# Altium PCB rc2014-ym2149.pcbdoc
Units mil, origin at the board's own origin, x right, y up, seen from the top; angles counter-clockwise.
Board outline 4542.51 x 2488.19 mil, 2 copper layers (Top Layer, Bottom Layer); 37 components, 100 nets, 242 pads, 3 vias.
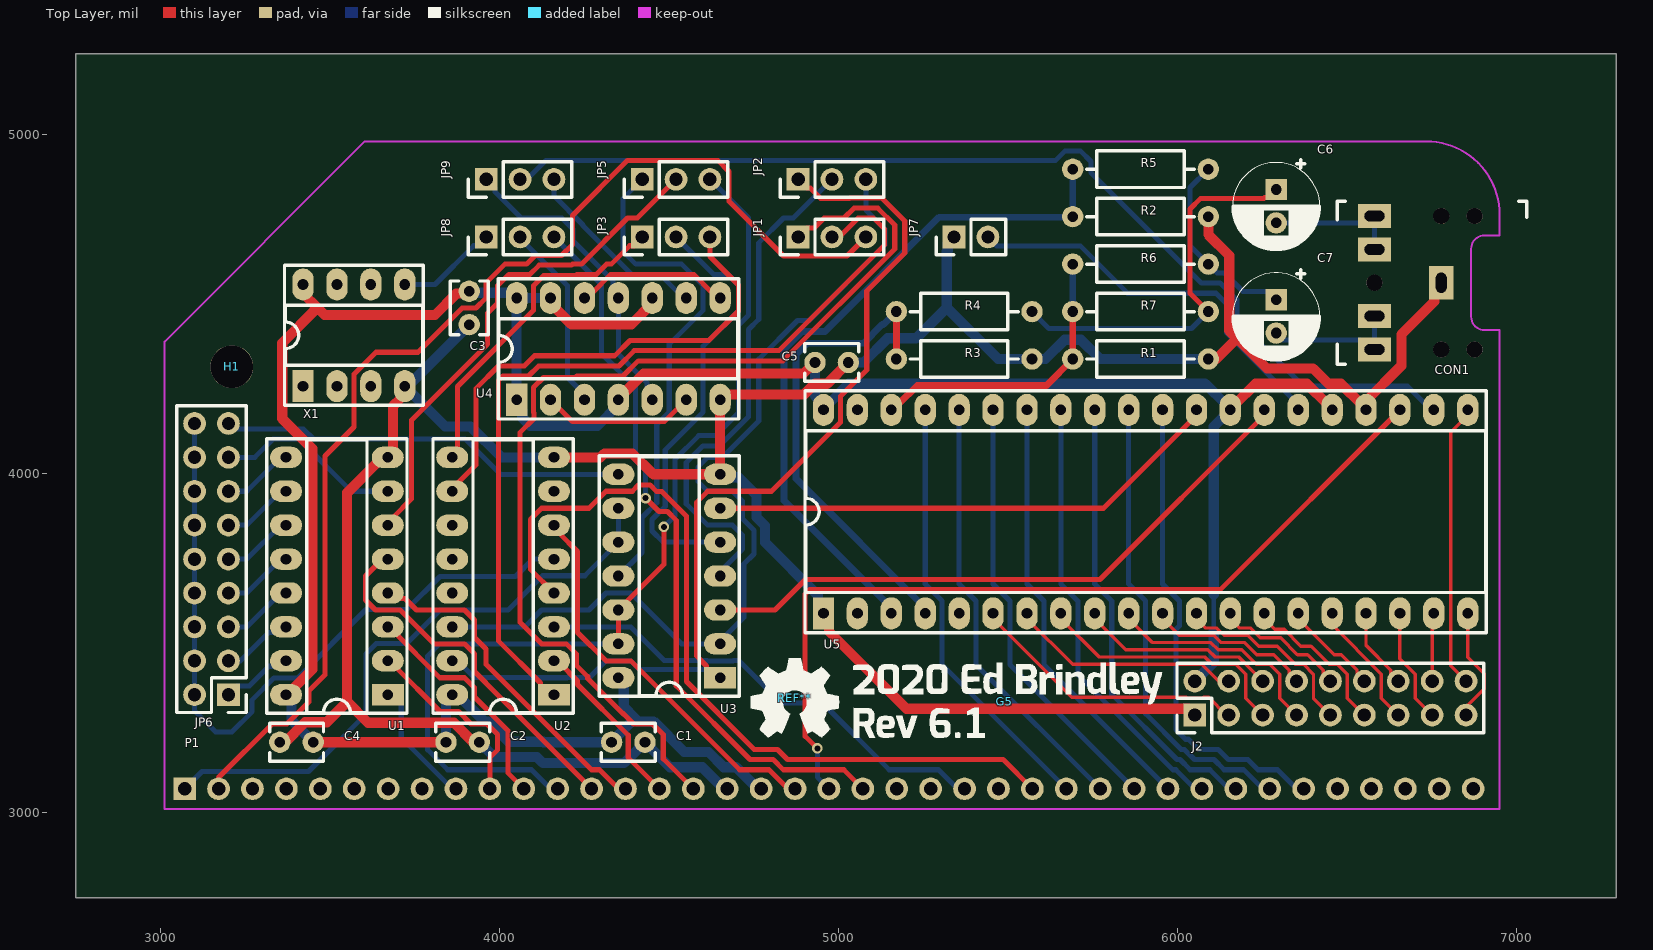
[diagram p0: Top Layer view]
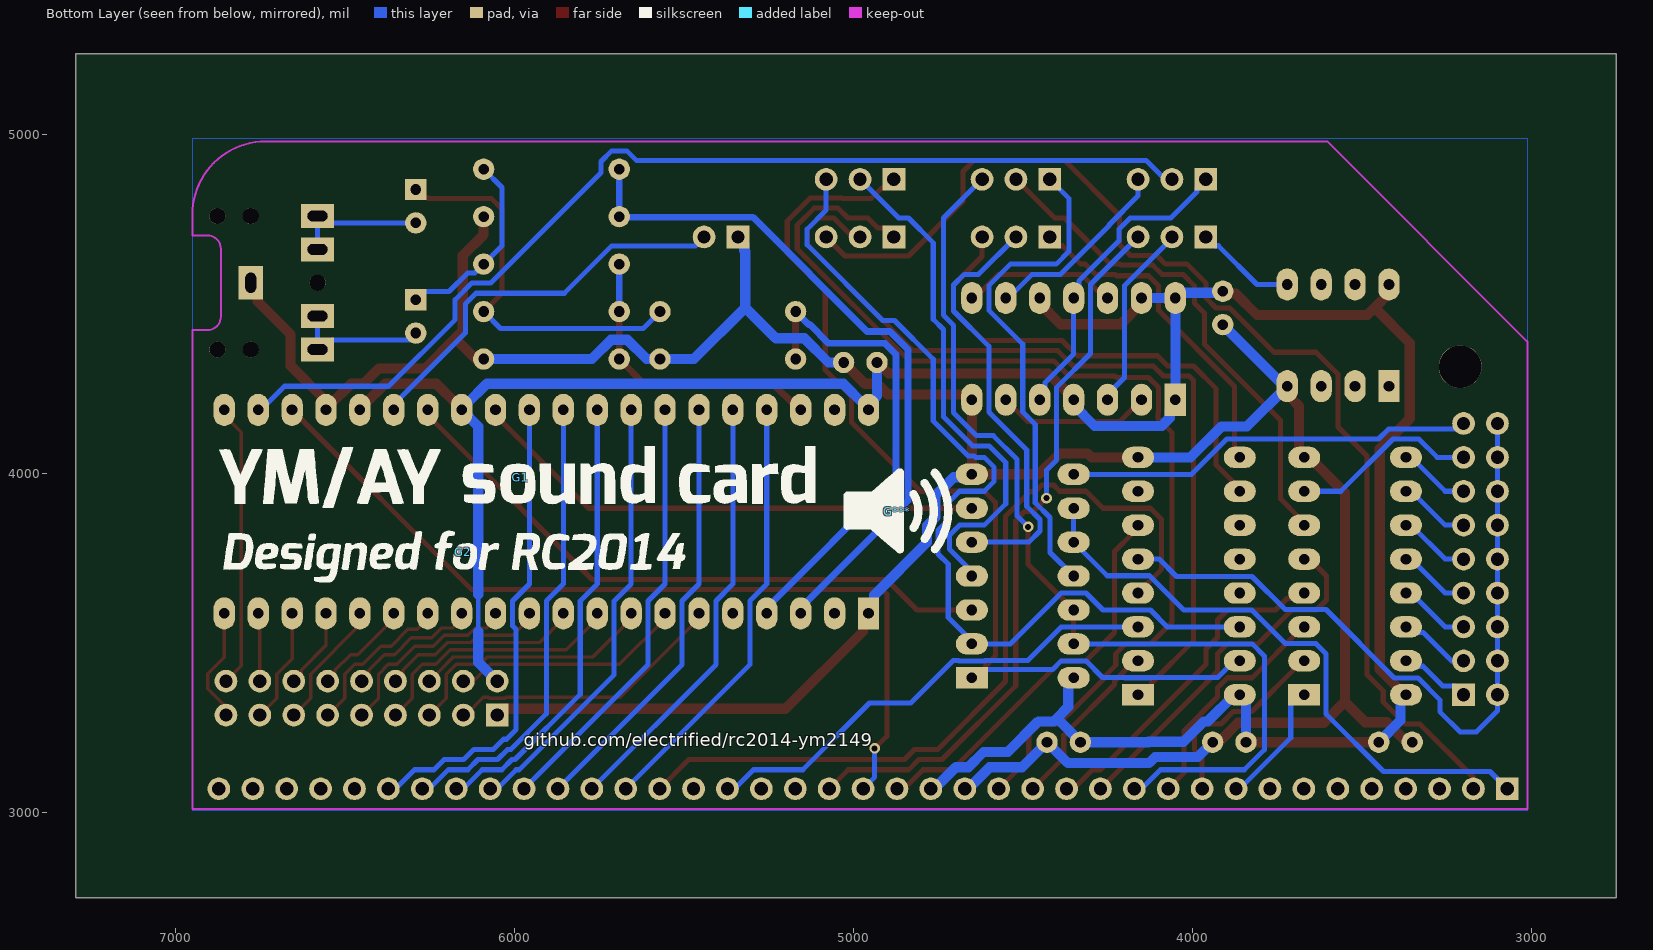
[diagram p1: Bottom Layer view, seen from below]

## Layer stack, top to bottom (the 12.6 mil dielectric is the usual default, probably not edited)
Top Layer: signal copper (thickness not stored)
Dielectric: dielectric 12.6, FR-4, Dk 4.8
Bottom Layer: signal copper (thickness not stored)

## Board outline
7292.51,2750 2750,2750 2750,5238.19 7292.51,5238.19

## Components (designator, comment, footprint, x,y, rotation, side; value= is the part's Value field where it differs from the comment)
C1 "0.1uF" Capacitor_THT:C_Disc_D3.8mm_W2.6mm_P2.50mm 4329.92,3208.19 r0 top
C2 "0.1uF" Capacitor_THT:C_Disc_D3.8mm_W2.6mm_P2.50mm 3841.49,3208.19 r0 top
C3 "0.1uF" Capacitor_THT:C_Disc_D3.8mm_W2.6mm_P2.50mm 3909.92,4538.19 r270 top
C4 "0.1uF" Capacitor_THT:C_Disc_D3.8mm_W2.6mm_P2.50mm 3449.92,3208.19 r180 top
C5 "0.1uF" Capacitor_THT:C_Disc_D3.8mm_W2.6mm_P2.50mm 4929.92,4328.19 r0 top
C6 "4.7uF" Capacitor_THT:CP_Radial_D6.3mm_P2.50mm 6289.91,4838.19 r270 top
C7 "4.7uF" Capacitor_THT:CP_Radial_D6.3mm_P2.50mm 6289.91,4513.19 r270 top
CON1 "SJ1-3523N" rc2014:Headphone_Jack_3.5mm_5_pin 6579.91,4563.19 r180 top
G1 "LOGO" rc2014:ym_text2 5979.92,3988.19 r180 bottom
G2 "LOGO" rc2014:designed_for_rc2014 6149.91,3768.19 r180 bottom
G5 "LOGO" rc2014:rev61 5489.92,3328.19 r0 top
G*** "LOGO" rc2014:speaker 4869.92,3888.19 r180 bottom
H1 "MountingHole" MountingHole:MountingHole_3.2mm_M3 3209.92,4315.67 r0 top
J2 "IO Out" Connector_PinHeader_2.54mm:PinHeader_2x09_P2.54mm_Vertical 6049.92,3288.19 r90 top
JP1 "MSX/ZX Spectrum" Connector_PinHeader_2.54mm:PinHeader_1x03_P2.54mm_Vertical 4879.92,4698.19 r90 top
JP2 "MSX/ZX Spectrum" Connector_PinHeader_2.54mm:PinHeader_1x03_P2.54mm_Vertical 4879.92,4868.19 r90 top
JP3 "MSX/ZX Spectrum" Connector_PinHeader_2.54mm:PinHeader_1x03_P2.54mm_Vertical 4419.92,4698.19 r90 top
JP5 "Upper/lower half" Connector_PinHeader_2.54mm:PinHeader_1x03_P2.54mm_Vertical 4419.92,4868.19 r90 top
JP6 "BASE ADDRESS" Connector_PinHeader_2.54mm:PinHeader_2x09_P2.54mm_Vertical 3199.92,3348.19 r180 top
JP7 "YM 1/2 CLK" Connector_PinHeader_2.54mm:PinHeader_1x02_P2.54mm_Vertical 5339.92,4698.19 r90 top
JP8 "Use bus clock" Connector_PinHeader_2.54mm:PinHeader_1x03_P2.54mm_Vertical 3959.92,4698.19 r90 top
JP9 "CLOCK DIVIDE 1/2 or 1/4" Connector_PinHeader_2.54mm:PinHeader_1x03_P2.54mm_Vertical 3959.92,4868.19 r90 top
P1 "RC2014 BUS" rc2014:PinHeader_1x39_P2.54mm_Vertical 3070.87,3070.87 r90 top
R1 "3K" Resistor_THT:R_Axial_DIN0207_L6.3mm_D2.5mm_P10.16mm_Horizontal 5689.92,4338.19 r0 top
R2 "3K" Resistor_THT:R_Axial_DIN0207_L6.3mm_D2.5mm_P10.16mm_Horizontal 5689.92,4758.19 r0 top
R3 "3K" Resistor_THT:R_Axial_DIN0207_L6.3mm_D2.5mm_P10.16mm_Horizontal 5169.92,4338.19 r0 top
R4 "1K" Resistor_THT:R_Axial_DIN0207_L6.3mm_D2.5mm_P10.16mm_Horizontal 5569.92,4478.19 r180 top
R5 "1K" Resistor_THT:R_Axial_DIN0207_L6.3mm_D2.5mm_P10.16mm_Horizontal 6089.92,4898.19 r180 top
R6 "1K6" Resistor_THT:R_Axial_DIN0207_L6.3mm_D2.5mm_P10.16mm_Horizontal 6089.92,4618.19 r180 top
R7 "1K6" Resistor_THT:R_Axial_DIN0207_L6.3mm_D2.5mm_P10.16mm_Horizontal 6089.92,4478.19 r180 top
REF** "OSHW-Symbol_6.7x6mm_SilkScreen" Symbol:OSHW-Symbol_6.7x6mm_SilkScreen 4869.92,3338.19 r0 top
U1 "74HCT138" Package_DIP:DIP-16_W7.62mm_Socket_LongPads 3669.92,3348.19 r180 top
U2 "74HCT138" Package_DIP:DIP-16_W7.62mm_Socket_LongPads 4159.92,3348.19 r180 top
U3 "74HCT00" Package_DIP:DIP-14_W7.62mm_Socket_LongPads 4649.92,3398.19 r180 top
U4 "74HCT74" Package_DIP:DIP-14_W7.62mm_Socket_LongPads 4049.92,4218.19 r90 top
U5 "YM2149" Package_DIP:DIP-40_W15.24mm_Socket_LongPads 4954.92,3588.19 r90 top
X1 "CXO_DIP8" Package_DIP:DIP-8_W7.62mm_Socket_LongPads 3419.92,4258.19 r90 top

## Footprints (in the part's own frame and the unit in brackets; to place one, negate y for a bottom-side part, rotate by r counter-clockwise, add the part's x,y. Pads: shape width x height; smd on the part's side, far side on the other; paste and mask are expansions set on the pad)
Capacitor_THT:C_Disc_D3.8mm_W2.6mm_P2.50mm [mm]
  round 1.6 hole 0.8: 1(0,0) 2(2.5,0)
  silkscreen extent -0.77,-1.42 3.27,1.42
Capacitor_THT:CP_Radial_D6.3mm_P2.50mm [mm]
  rect 1.6x1.6 hole 0.8: 1(0,0)
  round 1.6 hole 0.8: 2(2.5,0)
  silkscreen extent -2.25,-3.27 4.52,3.27
Connector_PinHeader_2.54mm:PinHeader_1x02_P2.54mm_Vertical [mm]
  rect 1.7x1.7 hole 1: 1(0,0)
  round 1.7 hole 1: 2(0,-2.54)
  silkscreen extent -1.33,-3.87 1.33,1.33
Connector_PinHeader_2.54mm:PinHeader_1x03_P2.54mm_Vertical [mm]
  rect 1.7x1.7 hole 1: 1(0,0)
  round 1.7 hole 1: 2(0,-2.54) 3(0,-5.08)
  silkscreen extent -1.33,-6.41 1.33,1.33
Connector_PinHeader_2.54mm:PinHeader_2x09_P2.54mm_Vertical [mm]
  rect 1.7x1.7 hole 1: 1(0,0)
  round 1.7 hole 1: 2(2.54,0) 3(0,-2.54) 4(2.54,-2.54) 5(0,-5.08) 6(2.54,-5.08) 7(0,-7.62) 8(2.54,-7.62) 9(0,-10.16) 10(2.54,-10.16) 11(0,-12.7) 12(2.54,-12.7) 13(0,-15.24) 14(2.54,-15.24) 15(0,-17.78) 16(2.54,-17.78) 17(0,-20.32) 18(2.54,-20.32)
  silkscreen extent -1.33,-21.65 3.87,1.33
MountingHole:MountingHole_3.2mm_M3 [mm]
  round 3.2 hole 3.2 unplated: 1(0,0)
Package_DIP:DIP-8_W7.62mm_Socket_LongPads [mm]
  rect 2.4x1.6 hole 0.8: 1(0,0)
  oval 2.4x1.6 hole 0.8: 2(0,-2.54) 3(0,-5.08) 4(0,-7.62) 5(7.62,-7.62) 6(7.62,-5.08) 7(7.62,-2.54) 8(7.62,0)
  silkscreen extent -1.44,-9.01 9.06,1.39
Package_DIP:DIP-14_W7.62mm_Socket_LongPads [mm]
  rect 2.4x1.6 hole 0.8: 1(0,0)
  oval 2.4x1.6 hole 0.8: 2(0,-2.54) 3(0,-5.08) 4(0,-7.62) 5(0,-10.16) 6(0,-12.7) 7(0,-15.24) 8(7.62,-15.24) 9(7.62,-12.7) 10(7.62,-10.16) 11(7.62,-7.62) 12(7.62,-5.08) 13(7.62,-2.54) 14(7.62,0)
  silkscreen extent -1.44,-16.63 9.06,1.39
Package_DIP:DIP-16_W7.62mm_Socket_LongPads [mm]
  rect 2.4x1.6 hole 0.8: 1(0,0)
  oval 2.4x1.6 hole 0.8: 2(0,-2.54) 3(0,-5.08) 4(0,-7.62) 5(0,-10.16) 6(0,-12.7) 7(0,-15.24) 8(0,-17.78) 9(7.62,-17.78) 10(7.62,-15.24) 11(7.62,-12.7) 12(7.62,-10.16) 13(7.62,-7.62) 14(7.62,-5.08) 15(7.62,-2.54) 16(7.62,0)
  silkscreen extent -1.44,-19.17 9.06,1.39
Package_DIP:DIP-40_W15.24mm_Socket_LongPads [mm]
  rect 2.4x1.6 hole 0.8: 1(0,0)
  oval 2.4x1.6 hole 0.8: 2(0,-2.54) 3(0,-5.08) 4(0,-7.62) 5(0,-10.16) 6(0,-12.7) 7(0,-15.24) 8(0,-17.78) 9(0,-20.32) 10(0,-22.86) 11(0,-25.4) 12(0,-27.94) 13(0,-30.48) 14(0,-33.02) 15(0,-35.56) 16(0,-38.1) 17(0,-40.64) 18(0,-43.18) 19(0,-45.72) 20(0,-48.26) 21(15.24,-48.26) 22(15.24,-45.72) 23(15.24,-43.18) 24(15.24,-40.64) 25(15.24,-38.1) 26(15.24,-35.56) 27(15.24,-33.02) 28(15.24,-30.48) 29(15.24,-27.94) 30(15.24,-25.4) 31(15.24,-22.86) 32(15.24,-20.32) 33(15.24,-17.78) 34(15.24,-15.24) 35(15.24,-12.7) 36(15.24,-10.16) 37(15.24,-7.62) 38(15.24,-5.08) 39(15.24,-2.54) 40(15.24,0)
  silkscreen extent -1.44,-49.65 16.68,1.39
rc2014:designed_for_rc2014 [mil]
  silkscreen extent -707,-88 654,63
rc2014:Headphone_Jack_3.5mm_5_pin [mm]
  round 1.2 hole 1.2 unplated: 1(-7.5,-5) 2(-5,5) 3(-5,-5) 4(0,0) 5(-7.5,5)
  rect 2.5x1.8 hole 0.8 slot 1.5 at 0 deg: R(0,5) RN(0,2.5) T(0,-5) TN(0,-2.5)
  rect 1.8x2.5 hole 0.8 slot 1.5 at 90 deg: S(-5,0)
  silkscreen extent -11.4,-6.1 2.8,6.1
rc2014:PinHeader_1x39_P2.54mm_Vertical [mm]
  rect 1.7x1.7 hole 1: 1(0,0)
  round 1.7 hole 1: 2(0,-2.54) 3(0,-5.08) 4(0,-7.62) 5(0,-10.16) 6(0,-12.7) 7(0,-15.24) 8(0,-17.78) 9(0,-20.32) 10(0,-22.86) 11(0,-25.4) 12(0,-27.94) 13(0,-30.48) 14(0,-33.02) 15(0,-35.56) 16(0,-38.1) 17(0,-40.64) 18(0,-43.18) 19(0,-45.72) 20(0,-48.26) 21(0,-50.8) 22(0,-53.34) 23(0,-55.88) 24(0,-58.42) 25(0,-60.96) 26(0,-63.5) 27(0,-66.04) 28(0,-68.58) 29(0,-71.12) 30(0,-73.66) 31(0,-76.2) 32(0,-78.74) 33(0,-81.28) 34(0,-83.82) 35(0,-86.36) 36(0,-88.9) 37(0,-91.44) 38(0,-93.98) 39(0,-96.52)
rc2014:rev61 [mil]
  silkscreen extent -447,-107 464,116
rc2014:speaker [mil]
  silkscreen extent -159,-123 161,127
rc2014:ym_text2 [mil]
  silkscreen extent -890,-89 867,93
Resistor_THT:R_Axial_DIN0207_L6.3mm_D2.5mm_P10.16mm_Horizontal [mm]
  round 1.6 hole 0.8: 1(0,0) 2(10.16,0)
  silkscreen extent 1.04,-1.37 9.12,1.37
Symbol:OSHW-Symbol_6.7x6mm_SilkScreen [mil]
  silkscreen extent -130,-116 131,117

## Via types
v1: diameter 31.5, hole 17.72, Top Layer to Bottom Layer, 3 vias

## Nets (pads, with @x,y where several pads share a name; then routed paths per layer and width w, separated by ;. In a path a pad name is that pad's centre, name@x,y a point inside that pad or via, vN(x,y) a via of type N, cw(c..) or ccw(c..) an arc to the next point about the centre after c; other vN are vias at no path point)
/A0: JP1.1 P1.16 | length 3134.1
  Top Layer w15: P1.16 4482.34,3159.39 4482.34,3230.55 4450.71,3262.19 4394.72,3262.19 4364.71,3292.19 4363.8,3292.19 4259.67,3396.32 4259.67,3401.43 4225.67,3435.44 4225.67,3468.9 4196.38,3498.19 4123.46,3498.19 4060.17,3561.48 4060.17,4121.97 4101.02,4162.82 4101.02,4179.06 4099.92,4180.17 4099.92,4254.65 4129.21,4283.93 4223.55,4283.93 4227.55,4287.93 4363.91,4287.93 4408.91,4332.94 4834.88,4332.94 5164.92,4662.98 5164.92,4733.39 5115.13,4783.19 5044.71,4783.19 5015.68,4754.15 4956.74,4754.15 4926.73,4724.15 4913.38,4724.15 4905.88,4724.15 JP1.1
/A1: P1.15 U2.2 | length 515.3
  Top Layer w15: U2.2 4175.67,3448.19 4175.67,3443.01 4229.67,3389.01 4229.67,3378.04 4379.13,3228.57 4379.13,3162.6 P1.15
/A2: P1.14 U1.4 | length 996.9
  Top Layer w15: U1.4 3685.67,3648.19 3701.66,3632.19 3720.46,3632.19 3754.47,3598.19 3896.38,3598.19 3925.67,3568.9 3925.67,3516.99 3959.67,3482.98 3959.67,3437.87 4270.71,3126.83 4294.04,3126.83 4350.01,3070.87 P1.14
/A3: P1.13 U1.5 | length 1085.4
  Top Layer w15: U1.5 3654.17,3748.19 3604.17,3698.19 3604.17,3627.48 3633.46,3598.19 3706.38,3598.19 3806.38,3498.19 3896.38,3498.19 3925.67,3468.9 3925.67,3416.99 3959.67,3382.98 3959.67,3382.06 P1.13
/A4: JP5.3 P1.12 U3.12 U3.13 | length 2889.7
  Top Layer w15: U3.13 U3.12 4483.99,3732.26 v1(4483.99,3843.19)
  Bottom Layer w15: P1.12 4150.01,3070.87 4094.05,3126.83 3846.48,3126.83 3787.49,3185.82 3787.49,3462.22 3823.46,3498.19 4334.17,3498.19 U3.13 ; v1(4483.99,3843.19) 4516.43,3875.63 4516.43,4041.68 4586.95,4112.19 4636.04,4112.19 4703.92,4180.07 4703.92,4437.64 4733.92,4467.64 4733.92,4754.18 JP5.3
/A5: P1.11 U1.3 | length 695.3
  Top Layer w15: U1.3 3685.67,3548.19 3685.67,3535.98 3823.46,3398.19 3896.38,3398.19 3925.67,3368.9 3925.67,3341.24 4023.92,3242.98 4023.92,3117.81 P1.11
/A6: P1.10 U1.2 | length 590.3
  Top Layer w15: U1.2 3685.67,3448.19 3685.67,3436.46 3823.6,3298.52 3878.91,3298.52 3915.25,3262.19 3962.29,3262.19 3993.92,3230.55 3993.92,3185.82 3970.86,3162.77 P1.10
/A7: P1.9 U1.1 | length 372.9
  Bottom Layer w15: U1.1 3709.66,3324.19 3709.66,3316.69 3709.66,3221.22 3860.02,3070.87 P1.9
/A14: JP1.3 P1.2 | length 3451.7
  Top Layer w15: P1.2 3170.87,3103.93 3329.13,3262.19 3372,3262.19 3436.81,3327 3436.81,3359.32 3484.67,3407.18 3484.67,4052.23 3569.92,4137.47 3569.92,4293.23 3634.88,4358.19 3758.75,4358.19 3889.53,4488.97 3930.31,4488.97 3959.13,4517.8 3959.13,4561.95 4015.12,4617.94 4078.76,4617.94 4104.47,4643.65 ; 4104.48,4643.65 4182.51,4643.65 4214.46,4675.6 4214.46,4761.48 4377.13,4924.15 4643.1,4924.15 4675.89,4891.37 4675.89,4803.46 4837.13,4642.22 5023.95,4642.22 JP1.3
/A15: P1.1 U3.9 U3.10 | length 1784.3
  Bottom Layer w15: P1.1 3121.83,3121.83 3436.08,3121.83 3605.18,3290.93 3605.18,3468.48 3635.88,3499.19 3725.88,3499.19 3824.88,3598.19 4024.88,3598.19 4125.88,3699.19 4250.92,3699.19 U3.10 U3.9
/BC1: U3.6 U5.29 | length 1534.3
  Top Layer w15: U3.6 4665.67,3898.19 5780.66,3898.19 6054.92,4172.44 U5.29
/BDIR: U3.3 U5.27 | length 1858.6
  Top Layer w15: U3.3 4665.67,3598.19 4811.92,3598.19 4901.67,3687.94 5770.42,3687.94 6254.91,4172.44 U5.27
/BUSCLK: JP8.3 P1.21 | length 2163.9
  Top Layer w15: v1(4429.92,3928.08) 4469.57,3888.43 4494.81,3888.43 4520.66,3862.58 4520.66,3374.45 4738.27,3156.84 4806.47,3156.84 4836.48,3126.83 5014.89,3126.83 P1.21
  Bottom Layer w15: JP8.3 4299.92,4558.19 4299.92,4354.65 4399.92,4254.65 4399.92,4040.3 4429.92,4010.3 v1(4429.92,3928.08)
/CH_A: R2.1 R5.2 U5.3 | length 2062.9
  Bottom Layer w20: U5.3 5154.92,3603.94 4838.41,3920.44 4838.41,4366.09 4892.02,4419.69 4959.13,4419.69 5296.09,4756.65 5688.38,4756.65 R2.1 R5.2
/CH_B: R3.1 R4.2 U5.4 | length 1410.4
  Top Layer w20: R3.1 R4.2
  Bottom Layer w20: R4.2 5131.42,4439.69 5127.87,4439.69 5072.87,4384.69 4906.52,4384.69 4873.42,4351.59 4873.42,3985.43 5254.92,3603.94 U5.4
/CH_C: R1.1 R6.2 R7.2 U5.38 | length 886.4
  Top Layer w20: U5.38 5154.92,4203.93 5175.02,4203.93 5231.52,4260.43 5612.16,4260.43 R1.1 R7.2
  Bottom Layer w20: R7.2 R6.2
/D0: P1.27 U5.37 | length 1289.6
  Bottom Layer w15: U5.37 5254.92,4172.44 5254.92,3674.65 5304.92,3624.65 5304.92,3436.81 P1.27
/D1: P1.28 U5.36 | length 1289.6
  Bottom Layer w15: U5.36 5354.92,4172.44 5354.92,3674.65 5404.92,3624.65 5404.92,3436.81 P1.28
/D2: P1.29 U5.35 | length 1289.6
  Bottom Layer w15: U5.35 5454.92,4172.44 5454.92,3674.65 5504.92,3624.65 5504.92,3436.81 P1.29
/D3: P1.30 U5.34 | length 1289.6
  Bottom Layer w15: U5.34 5554.92,4172.44 5554.92,3674.65 5604.92,3624.65 5604.92,3436.81 P1.30
/D4: P1.31 U5.33 | length 1307
  Bottom Layer w15: U5.33 5654.92,4172.44 5654.92,3674.65 5704.92,3624.65 5704.92,3407.14 5985.22,3126.83 5994.04,3126.83 6050.01,3070.87 P1.31
/D5: P1.32 U5.32 | length 1340.7
  Bottom Layer w15: U5.32 5754.92,4172.44 5754.92,3674.65 5804.92,3624.65 5804.92,3349.57 5997.65,3156.84 6006.47,3156.84 6036.47,3126.83 6094.04,3126.83 6150.01,3070.87 P1.32
/D6: P1.33 U5.31 | length 1374.4
  Bottom Layer w15: U5.31 5854.92,4172.44 5854.92,3674.65 5904.92,3624.65 5904.92,3292 6010.08,3186.84 6018.9,3186.84 6048.9,3156.84 6106.47,3156.84 6136.47,3126.83 6194.04,3126.83 6250.01,3070.87 P1.33
/D7: P1.34 U5.30 | length 1417.2
  Bottom Layer w15: U5.30 5954.92,4172.44 5954.92,3674.65 6004.92,3624.65 6004.92,3551.73 5993.95,3540.76 5993.95,3245.4 6022.5,3216.85 6031.33,3216.85 6061.33,3186.84 6118.9,3186.84 6148.9,3156.84 6206.47,3156.84 6236.47,3126.83 6294.04,3126.83 6350.01,3070.87 P1.34
/IOA0: J2.18 U5.21 | length 839.3
  Top Layer w10: J2.18 6804.91,3433.19 6804.91,4122.44 6854.91,4172.44 U5.21
/IOA1: J2.17 U5.20 | length 342.2
  Top Layer w10: J2.17 6849.91,3312.57 6903.38,3366.04 6903.38,3410.33 6854.91,3458.8 6854.91,3572.44 U5.20
/IOA2: J2.16 U5.19 | length 202.1
  Top Layer w10: J2.16 6749.91,3567.44 6754.91,3572.44 U5.19
/IOA3: J2.15 U5.18 | length 339.3
  Top Layer w10: U5.18 6654.91,3572.44 6654.91,3453.9 6699.91,3408.9 6699.91,3338.19 J2.15
/IOA4: J2.14 U5.17 | length 239.3
  Top Layer w10: U5.17 6554.91,3572.44 6554.91,3494.16 6628.39,3420.69 6628.39,3409.72 J2.14
/IOA5: J2.13 U5.16 | length 380.8
  Top Layer w10: U5.16 6454.91,3572.44 6454.91,3553.9 6599.91,3408.9 6599.91,3338.19 J2.13
/IOA6: J2.12 U5.15 | length 293.5
  Top Layer w10: U5.15 6354.91,3572.44 6460.69,3466.66 6482.42,3466.66 6528.39,3420.69 6528.39,3409.72 J2.12
/IOA7: J2.11 U5.14 | length 469.9
  Top Layer w10: U5.14 6254.91,3572.44 6286.06,3541.29 6313.33,3541.29 6362.96,3491.66 6392.78,3491.66 6446.25,3438.19 6470.63,3438.19 6499.91,3408.9 6499.91,3338.19 J2.11
/IOB0: J2.10 U5.13 | length 393.5
  Top Layer w10: U5.13 6154.91,3572.44 6182.5,3544.86 6214.81,3544.86 6243.3,3516.37 6303.01,3516.37 6352.71,3466.66 6382.42,3466.66 6428.39,3420.69 6428.39,3409.72 J2.10
/IOB1: J2.9 U5.12 | length 569.9
  Top Layer w10: U5.12 6054.92,3572.44 6082.5,3544.86 6114.81,3544.86 6136.18,3523.49 6205.96,3523.49 6238.01,3491.44 6292.68,3491.44 6345.93,3438.19 6370.63,3438.19 6399.91,3408.9 6399.91,3338.19 J2.9
/IOB2: J2.8 U5.11 | length 493.4
  Top Layer w10: U5.11 5954.92,3572.44 6003.87,3523.49 6105.96,3523.49 6127.32,3502.12 6197.11,3502.12 6232.72,3466.51 6282.36,3466.51 6328.24,3420.63 6328.24,3409.87 J2.8
/IOB3: J2.7 U5.10 | length 669.9
  Top Layer w10: U5.10 5854.92,3572.44 5925.23,3502.12 6097.11,3502.12 6118.47,3480.75 6188.26,3480.75 6230.82,3438.19 6270.63,3438.19 6299.91,3408.9 6299.91,3338.19 J2.7
/IOB4: J2.6 U5.9 | length 587.5
  Top Layer w10: U5.9 5754.92,3572.44 5846.6,3480.75 6088.26,3480.75 6109.62,3459.39 6179.41,3459.39 6221.12,3417.68 6221.12,3416.99 J2.6
/IOB5: J2.5 U5.8 | length 769.8
  Top Layer w10: U5.8 5654.92,3572.44 5767.97,3459.39 6079.41,3459.39 6100.78,3438.02 6170.56,3438.02 6199.75,3408.83 6199.75,3338.36 J2.5
/IOB6: J2.4 U5.7 | length 687.1
  Top Layer w10: U5.7 5554.92,3572.44 5689.34,3438.02 6070.56,3438.02 6120.39,3388.19 J2.4
/IOB7: J2.3 U5.6 | length 830.2
  Top Layer w10: U5.6 5454.92,3572.44 5687.08,3340.27 6024.16,3340.27 6026.25,3338.19 6029.2,3338.19 6070.63,3338.19 6073.58,3338.19 6075.67,3340.27 6091.09,3340.27 6143.18,3288.19 J2.3
/M1: P1.19 U2.6 | length 1186.5
  Top Layer w15: U2.6 4175.67,3848.19 4175.67,3824.55 4229.67,3770.55 4229.67,3531.98 4313.46,3448.19 4386.38,3448.19 4707.73,3126.83 4794.04,3126.83 4850.01,3070.87 P1.19
/YMCLK: JP9.2 U5.22 | length 3109
  Bottom Layer w15: JP9.2 4080.77,4868.19 4136.74,4924.15 4436.56,4924.15 4444.06,4924.15 4896.56,4924.15 4904.06,4924.15 5639.52,4924.15 5667.55,4952.19 5712.28,4952.19 5743.92,4920.55 5743.92,4887.82 6067.55,4564.19 6069.55,4562.19 6124.71,4562.19 6173.92,4512.98 6173.92,4454.39 6370.38,4257.93 6677.28,4257.93 6731.28,4203.93 6754.91,4203.93 U5.22
/~{CS}: JP6.2 JP6.4 JP6.6 JP6.8 JP6.10 JP6.12 JP6.14 JP6.16 JP6.18 U2.5 | length 2165.1
  Bottom Layer w15: JP6.18 JP6.16 JP6.14 JP6.12 JP6.10 JP6.8 JP6.6 JP6.4 JP6.2 3099.92,3300.86 3162.59,3238.19 3209.92,3238.19 3269.92,3298.19 3269.92,3333.23 3333.88,3397.18 3403.96,3397.18 3605.96,3599.19 3725.88,3599.19 3823.88,3697.18 4046.67,3697.18 4097.68,3748.19 U2.5
/~{IORQ}: P1.26 U2.4 | length 2425.1
  Top Layer w15: U2.4 4090.17,3717.94 4090.17,3864.9 4123.46,3898.19 4263.46,3898.19 4313.46,3948.19 4390.88,3948.19 4409.1,3966.42 4443.68,3966.42 4463.15,3946.95 4478.48,3946.95 4550.5,3874.94 4550.5,3387.04 4750.7,3186.84 4818.9,3186.84 4848.91,3156.84 5484.89,3156.84 P1.26
/~{RESET}: P1.20 U5.23 | length 2582
  Top Layer w15: v1(4936.7,3190.07) 4900.92,3225.85 4900.92,3644.75 4914.1,3657.94 6124.66,3657.94 U5.23
  Bottom Layer w15: v1(4936.7,3190.07) 4936.7,3105.03 P1.20
/~{WR}: P1.24 U2.3 | length 1409.6
  Bottom Layer w15: U2.3 4175.67,3548.19 4386.38,3548.19 4485.28,3449.29 4610.8,3449.29 4611.9,3448.19 4613.46,3448.19 4687.94,3448.19 4689.04,3449.29 4705.28,3449.29 4830.55,3324.03 4951.61,3324.03 5148.81,3126.83 5294.04,3126.83 5350.01,3070.87 P1.24
GND: C1.2 C2.2 C3.2 C4.2 C5.2 CON1.S J2.1 JP7.1 P1.17 R1.2 R2.2 R3.2 U1.8 U2.8 U3.7 U4.7 U5.1 U5.24 X1.4 | length 9194.5
  Top Layer w30: C4.2 3366.99,3208.19 3425.63,3266.83 3489.7,3266.83 3549.98,3327.11 ; X1.4 3707.42,4245.69 3707.42,4221.94 3685.67,4200.19 3685.67,4048.19 U1.8 3654.17,4048.19 3549.98,3943.99 3549.98,3327.11 ; C2.2 3922.34,3208.19 3865.17,3265.35 3611.73,3265.35 3549.98,3327.11 ; U2.8 4175.67,4048.19 4297.2,4048.19 4308.7,4059.69 4391.14,4059.69 4449.35,4001.47 4450.86,4001.47 4454.15,3998.19 4634.17,3998.19 U3.7 4649.92,4202.44 U4.7 4649.92,4233.93 4897.94,4233.93 4929.44,4265.43 4965.59,4265.43 C5.2 ; U5.1 4971.41,3555.94 4971.41,3540.94 4971.41,3534.73 4980.2,3525.94 5199.49,3306.65 6016.45,3306.65 6031.45,3306.65 J2.1 ; R1.2 6113.27,4338.19 6174.26,4399.17 ; R2.2 6089.92,4705.16 6151.41,4643.66 6151.41,4422.02 6174.26,4399.17 ; U5.24 U5.24@6554.91,4203.93 ; CON1.S 6756.33,4528.97 6756.33,4513.97 6756.33,4507.76 6659.13,4410.56 6659.13,4318.47 6554.91,4214.26 U5.24@6554.91,4203.93 ; 6174.26,4399.17 6262.99,4310.44 6399.03,4310.44 6444.03,4265.43 6480.39,4265.43 6541.89,4203.93 U5.24@6554.91,4203.93
  Bottom Layer w30: C3.2 3728.34,4258.19 X1.4 3838.42,4139.69 3901.9,4139.69 3913.57,4139.69 4005.07,4048.19 4144.17,4048.19 U2.8 ; C2.2 3983.77,3164.34 4109.58,3164.34 4127.23,3146.69 4304.45,3146.69 4355.39,3146.69 4366.84,3146.69 C1.2 4502.2,3134.33 4597.15,3134.33 4660.62,3070.87 P1.17 ; U3.7 4665.67,3998.19 4674.16,3989.69 4703.57,3989.69 4757.17,3936.09 4757.17,3871.45 4782.17,3846.45 4782.17,3797.89 4938.42,3641.64 4938.42,3635.43 4938.42,3620.43 U5.1 ; C5.2 5072.94,4328.19 5144.44,4399.69 5228,4399.69 5318.18,4489.87 ; JP7.1 5321.45,4679.72 5321.45,4664.72 5321.45,4658.51 5318.18,4655.24 5318.18,4489.87 ; R1.2 5770.76,4338.19 5713.59,4395.35 5666.24,4395.35 5609.07,4338.19 R3.2 5469.87,4338.19 5318.18,4489.87
NET-(C6-PAD1): C6.1 R4.1 R7.1 | length 1163.7
  Top Layer w15: R7.1 6035.92,4532.19 6035.92,4780.55 6067.55,4812.19 6253.31,4812.19 6255.31,4814.19 6258.42,4814.19 6265.92,4814.19 C6.1
  Bottom Layer w15: R4.1 5619.58,4428.52 6040.25,4428.52 R7.1
NET-(C6-PAD2): C6.2 CON1.T CON1.TN | length 393.1
  Bottom Layer w15: C6.2 6530.7,4739.76 6538.2,4739.76 CON1.T 6579.91,4732.1 6579.91,4724.6 6579.91,4697.04 6579.91,4689.54 CON1.TN
NET-(C7-PAD1): C7.1 R5.1 R6.1 | length 568.2
  Bottom Layer w15: R5.1 6035.92,4844.19 6035.92,4672.19 R6.1 6115.91,4592.19 6137.14,4592.19 6192.15,4537.18 6258.42,4537.18 6265.92,4537.18 C7.1
NET-(C7-PAD2): C7.2 CON1.R CON1.RN | length 405.4
  Bottom Layer w15: C7.2 6310.41,4394.27 6530.7,4394.27 6538.2,4394.27 CON1.R 6579.91,4394.27 6579.91,4401.77 6579.91,4429.33 6579.91,4436.83 CON1.RN
NET-(JP1-PAD2): JP1.2 U2.1 | length 2543.7
  Top Layer w15: U2.1 4120.17,3372.18 4120.17,3379.68 4120.17,3382.79 3995.92,3507.05 3995.92,4274.75 4009.1,4287.93 4085.12,4287.93 4115.12,4317.94 4351.48,4317.94 4396.48,4362.94 4823.14,4362.94 5135.4,4675.2 5135.4,4721.17 5102.9,4753.67 5056.93,4753.67 5001.45,4698.19 JP1.2
NET-(JP2-PAD1): JP2.1 U2.15 U3.1 | length 2961.4
  Top Layer w15: U3.1 4610.17,3422.18 4610.17,3429.68 4610.17,3432.79 4580.17,3462.79 4580.17,3808 4580.34,3808.17 4580.34,3915.07 4584.17,3918.9 4613.46,3948.19 4801.38,3948.19 5004.92,4151.73 5004.92,4228.4 5082.34,4305.82 5082.34,4538.65 5194.44,4650.75 5194.44,4745.62 5127.35,4812.7 5032.48,4812.7 5031.99,4812.22 4946.49,4812.22 4916.49,4842.22 4913.38,4842.22 4905.88,4842.22 JP2.1
  Bottom Layer w15: U2.15 3875.67,3448.19 3924.57,3399.29 4120.8,3399.29 4121.9,3398.19 4196.38,3398.19 4197.94,3398.19 4199.04,3399.29 4264.56,3399.29 4313.46,3448.19 4386.38,3448.19 4412.38,3422.18 4602.67,3422.18 4610.17,3422.18 U3.1
NET-(JP2-PAD2): JP2.2 U3.4 | length 1541.3
  Bottom Layer w15: U3.4 4665.67,3698.19 4665.67,3727.47 4715.67,3777.47 4715.67,3818.9 4686.38,3848.19 4613.46,3848.19 4550.17,3911.48 4550.17,4032.98 4599.37,4082.19 4648.47,4082.19 4733.92,4167.64 4733.92,4425.21 4763.93,4455.21 4763.93,4680.95 4837.13,4754.15 4844.63,4754.15 4865.89,4754.15 JP2.2
NET-(JP2-PAD3): JP2.3 U2.14 U3.2 | length 2722.7
  Bottom Layer w15: U2.14 3875.67,3548.19 4073.46,3548.19 4123.46,3598.19 4263.46,3598.19 4313.46,3648.19 4386.38,3648.19 4536.38,3498.19 4634.17,3498.19 U3.2 4665.67,3498.19 4665.67,3521.82 4719.67,3575.82 4719.67,3733.39 4749.67,3763.39 4749.67,3832.98 4715.67,3866.99 4715.67,3918.9 4686.38,3948.19 4613.46,3948.19 4584.17,3977.47 4584.17,4018.9 4613.46,4048.19 4639.3,4048.19 4643.3,4052.19 4660.9,4052.19 4763.93,4155.21 4763.93,4337.57 4878.55,4452.19 4913.07,4452.19 5135.89,4675 5135.89,4721.37 5079.92,4777.34 JP2.3
NET-(JP3-PAD1): JP3.1 U2.9 | length 994.6
  Top Layer w15: U2.9 3875.67,4048.19 3875.67,4257.47 4099.92,4481.73 4099.92,4554.65 4129.21,4583.93 4223.55,4583.93 4227.55,4587.93 4285.12,4587.93 4315.12,4617.94 4329.06,4617.94 4383.35,4672.22 4386.45,4672.22 4393.95,4672.22 JP3.1
NET-(JP3-PAD2): JP3.2 U3.5 | length 1288
  Bottom Layer w15: JP3.2 4630.17,4587.93 4672.28,4587.93 4703.92,4556.3 4703.92,4480.07 4599.92,4376.07 4599.92,4181.73 4488.13,4069.94 4488.13,3903.97 4449.06,3864.89 4449.06,3831.13 4482,3798.19 U3.5
NET-(JP3-PAD3): JP3.3 U2.10 | length 1462.9
  Top Layer w15: U2.10 3875.67,3948.19 3875.67,3971.82 3929.67,4025.82 3929.67,4250.93 3996.68,4317.94 4072.69,4317.94 4102.69,4347.94 4339.05,4347.94 4384.05,4392.95 4616.79,4392.95 4703.92,4480.07 4703.92,4556.3 4619.92,4640.3 JP3.3
NET-(JP5-PAD1): JP5.1 U3.11 | length 1473.7
  Bottom Layer w15: U3.11 4419.64,3767.91 4419.64,3870.81 4463.15,3914.31 4463.15,4144.95 4499.92,4181.73 4499.92,4381.73 4599.92,4481.73 4599.92,4554.65 4536.63,4617.94 4401.41,4617.94 4363.95,4655.4 4363.95,4812.22 JP5.1
NET-(JP5-PAD2): JP5.2 U1.6 | length 1505.6
  Top Layer w15: U1.6 3685.67,3848.19 3685.67,3871.82 3739.67,3925.82 3739.67,4157.93 3963.92,4382.19 3963.92,4473.39 3993.92,4503.39 3993.92,4554.3 4027.55,4587.93 4089.17,4587.93 4116.31,4615.08 4212.26,4615.08 4215.12,4617.94 4240.91,4617.94 4377.13,4754.15 4405.89,4754.15 JP5.2
NET-(JP6-PAD1): JP6.1 U1.15 | length 211.4
  Bottom Layer w15: JP6.1 3225.89,3374.15 3233.39,3374.15 3261.34,3374.15 3319.38,3432.19 3338.18,3432.19 3354.17,3448.19 U1.15
NET-(JP6-PAD3): JP6.3 U1.14 | length 211.4
  Bottom Layer w15: JP6.3 3235.37,3448.19 3319.38,3532.19 3338.18,3532.19 3354.17,3548.19 U1.14
NET-(JP6-PAD5): JP6.5 U1.13 | length 211.4
  Bottom Layer w15: JP6.5 3254.17,3548.19 3354.17,3648.19 U1.13
NET-(JP6-PAD7): JP6.7 U1.12 | length 211.4
  Bottom Layer w15: JP6.7 3254.17,3648.19 3354.17,3748.19 U1.12
NET-(JP6-PAD9): JP6.9 U1.11 | length 211.4
  Bottom Layer w15: JP6.9 3254.17,3748.19 3354.17,3848.19 U1.11
NET-(JP6-PAD11): JP6.11 U1.10 | length 211.4
  Bottom Layer w15: JP6.11 3254.17,3848.19 3354.17,3948.19 U1.10
NET-(JP6-PAD13): JP6.13 U1.9 | length 211.4
  Bottom Layer w15: JP6.13 3254.17,3948.19 3354.17,4048.19 U1.9
NET-(JP6-PAD15): JP6.15 U1.7 | length 556.2
  Bottom Layer w15: JP6.15 3277.81,4048.19 3331.81,4102.19 3408.03,4102.19 3562.03,3948.19 3654.17,3948.19 U1.7
NET-(JP6-PAD17): JP6.17 U3.8 | length 1212.1
  Bottom Layer w15: JP6.17 3215.92,4132.19 3420.46,4132.19 3450.47,4102.19 3898.03,4102.19 4002.03,3998.19 4334.17,3998.19 U3.8
NET-(JP7-PAD2): JP7.2 U5.26 | length 1185.6
  Bottom Layer w15: JP7.2 5465.92,4672.19 5712.28,4672.19 5852.28,4532.19 6112.28,4532.19 6143.91,4500.55 6143.91,4414.93 6354.91,4203.93 U5.26
NET-(JP8-PAD1): JP8.1 X1.5 | length 298
  Bottom Layer w15: X1.5 3809.31,4558.19 3923.35,4672.22 3926.45,4672.22 3933.95,4672.22 JP8.1
NET-(JP8-PAD2): JP8.2 U4.3 | length 558.7
  Bottom Layer w15: JP8.2 4059.92,4694.65 4199.92,4554.65 4199.92,4283.93 4249.92,4233.93 U4.3
NET-(JP9-PAD1): JP9.1 U4.5 U4.11 | length 923.1
  Bottom Layer w15: JP9.1 3985.88,4842.22 3985.88,4834.72 3985.88,4831.61 3990.28,4827.22 4063.34,4754.15 4183.1,4754.15 4215.89,4721.37 4215.89,4686.76 4333.92,4568.73 4333.92,4549.93 4349.92,4533.93 U4.11 4349.92,4502.44 4349.92,4352.73 4433.92,4268.73 4433.92,4249.93 4449.92,4233.93 U4.5
NET-(JP9-PAD3): JP9.3 U4.9 | length 574.2
  Bottom Layer w15: JP9.3 4159.92,4819.77 4245.89,4733.8 4245.89,4731.03 4388.99,4587.93 4472.28,4587.93 4526.28,4533.93 4549.92,4533.93 U4.9
NET-(U4-PAD2): U4.2 U4.6 | length 453.6
  Top Layer w15: U4.2 4214.66,4153.44 4485.17,4153.44 U4.6
NET-(U4-PAD12): U4.8 U4.12 | length 476.2
  Top Layer w15: U4.12 4249.92,4533.93 4273.55,4533.93 4327.55,4587.93 4572.28,4587.93 4626.28,4533.93 4649.92,4533.93 U4.8
UNCONNECTED-(P1-PAD3): P1.3
UNCONNECTED-(P1-PAD4): P1.4
UNCONNECTED-(P1-PAD5): P1.5
UNCONNECTED-(P1-PAD6): P1.6
UNCONNECTED-(P1-PAD7): P1.7
UNCONNECTED-(P1-PAD8): P1.8
UNCONNECTED-(P1-PAD22): P1.22
UNCONNECTED-(P1-PAD23): P1.23
UNCONNECTED-(P1-PAD25): P1.25
UNCONNECTED-(P1-PAD35): P1.35
UNCONNECTED-(P1-PAD36): P1.36
UNCONNECTED-(P1-PAD37): P1.37
UNCONNECTED-(P1-PAD38): P1.38
UNCONNECTED-(P1-PAD39): P1.39
UNCONNECTED-(U2-PAD7): U2.7
UNCONNECTED-(U2-PAD11): U2.11
UNCONNECTED-(U2-PAD12): U2.12
UNCONNECTED-(U2-PAD13): U2.13
UNCONNECTED-(U5-PAD2): U5.2
UNCONNECTED-(U5-PAD5): U5.5
UNCONNECTED-(U5-PAD39): U5.39
UNCONNECTED-(X1-PAD1): X1.1
VCC: C1.1 C2.1 C3.1 C4.1 C5.1 J2.2 P1.18 U1.16 U2.16 U3.14 U4.1 U4.4 U4.10 U4.13 U4.14 U5.25 U5.28 U5.40 X1.8 | length 8408.8
  Top Layer w30: U1.16 3385.67,3348.19 3385.67,3361.22 3447.17,3422.72 3447.17,4073.66 3358.42,4162.41 3358.42,4385.58 3462.25,4489.41 ; X1.8 3419.92,4531.74 3462.25,4489.41 ; C4.1 C2.1 ; C3.1 3903,4531.26 3872.02,4531.26 3808.94,4468.19 3483.47,4468.19 3462.25,4489.41 ; U4.13 4149.92,4502.44 4211.42,4440.94 4224.45,4440.94 4388.42,4440.94 4449.92,4502.44 U4.10 ; U4.4 4349.92,4233.93 4362.95,4233.93 4424.45,4295.43 4895.8,4295.43 4910.8,4310.44 4912.17,4310.44 C5.1 ; U5.28 6154.91,4203.93 6167.94,4203.93 6229.44,4265.43 6380.39,4265.43 6441.89,4203.93 6454.91,4203.93 U5.25
  Bottom Layer w14.25: 6105.92,3534.19 6105.92,3644.19
  Bottom Layer w30: U1.16 3385.67,3348.19 3385.67,3272.44 C4.1 ; C2.1 3841.49,3345.51 3844.17,3348.19 U2.16 3875.67,3348.19 3954.17,3269.69 3965.39,3269.69 4025.74,3209.34 4128.22,3209.34 4129.38,3208.19 C1.1 4329.92,3209.88 4399.13,3279.09 ; C3.1 3914.17,4533.93 4049.92,4533.93 U4.14 ; U4.13 U4.14 ; U3.14 4365.67,3398.19 4365.67,3312.56 4399.13,3279.09 ; U4.4 4349.92,4202.44 4288.42,4140.94 4275.39,4140.94 4090.21,4140.94 4075.2,4155.94 4066.42,4164.73 4066.42,4170.94 4066.42,4185.94 U4.1 4049.92,4250.43 4049.92,4265.43 4049.92,4502.44 U4.14 ; P1.18 4760.62,3070.87 4697.15,3134.33 4660.8,3134.33 4615.79,3179.34 4544.17,3179.34 4453.82,3269.69 4408.54,3269.69 4399.13,3279.09 ; C5.1 4929.92,4228.93 U5.40@4954.92,4203.93 ; U5.40 U5.40@4954.92,4203.93 ; J2.2 6105.92,3444.19 6105.92,3534.19 ; 6105.92,3644.19 6105.92,3659.19 6105.92,4139.19 U5.28 6154.91,4203.93 6141.89,4203.93 6080.39,4265.43 5029.44,4265.43 4967.94,4203.93 U5.40@4954.92,4203.93
"": CON1.1 CON1.2 CON1.3 CON1.4 CON1.5 H1.1 X1.2 X1.3 X1.6 X1.7

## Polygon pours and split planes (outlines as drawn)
GND on Bottom Layer (solid, remove dead copper, pour order 0): 6949.91,3008.19 3009.92,3008.19 3009.92,4988.19 6949.91,4988.19

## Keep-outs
Board Outline Layer:
  lines w5.91 net "": 3011.81,3011.81 6948.81,3011.81 6948.81,4423.19 6904.91,4423.19 cw(c6904.91,4463.19) 6864.91,4463.19 6864.91,4663.19 cw(c6904.91,4663.19) 6904.91,4703.19 6948.81,4703.19 6948.81,4763.78 ccw(c6732.28,4763.78) 6732.28,4980.31 3602.36,4980.31 3011.81,4389.76 3011.81,3011.81

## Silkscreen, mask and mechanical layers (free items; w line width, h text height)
Bottom Silkscreen Layer:
  text "github.com/electrified/rc2014-ym2149" at 5971.69,3196.44 h38.33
